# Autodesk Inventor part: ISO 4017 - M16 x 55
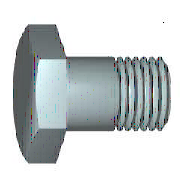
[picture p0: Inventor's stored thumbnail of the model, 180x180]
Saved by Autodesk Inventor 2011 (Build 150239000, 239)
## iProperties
Created: 2009-02
Part Number: ISO 4017 - M16 x 55
Material: Stainless Steel, 440C
Description: Hexagon head screws
Document SubType Name: Modeling
Standard: ISO 4017
Designer: V.de Jong
Standard Revision: Third edition 1999-08-15
Standards Organization: ISO
Language: en-US
Size Designation: M16 x 55
Categories: <MemberInstance><Categories><Category DisplayName="Fasteners" InternalName="e4da775c-781d-43d5-af7c-5136215cf5a6" Mnemonic="FSTN"><Category DisplayName="Bolts"
Density: 7.75 g/cm^3
IsCustomPart: 0
Author: V.de Jong
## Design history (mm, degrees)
body "Solid1"
workplane "Work Plane1"
revolve "Body" stored, may be unused: angle "d12" = 90 deg
sketch "Sketch2"
  geometry: L1 (0, 13.856)-(12, 6.928); L2 (12, 6.928)-(12, -6.928); L3 (12, -6.928)-(0, -13.856); L4 (0, -13.856)-(-12, -6.928); L5 (-12, -6.928)-(-12, 6.928); L6 (-12, 6.928)-(0, 13.856); 2 further points
  constraints: 12 end point, 1 coincident, 1 vertical, 11 other
  dimensions: "d11" = 24 distance between parallel lines of L5 L2 (= SW)
extrude "Head" join sketch "Sketch2" distance "d3" = 9.2 (= KOH - SD); taper "d4" = 0 deg
revolve "Chamfer1" stored, may be unused: angle "d21" = 90 deg
feature "Thread" dims "d15" = 49 (= GEL), "d16" = 0
chamfer "Chamfer2" distance "d6" = 1.2269 (= -0.5 x SPD + 0.5 x GD); stored, may be unused: second distance "d7" = 1.227 (computed from GUL), angle "d55" = 45 deg
sketch "Sketch1"
  geometry: L1 (0, 11.245)-(0, 8); L2 (6, 8)-(55, 8); L3 (55, 8)-(55, 0); L4 (55, 0)-(-0.8, 0); L5 (-11.96, 0)-(66.16, 0) reference; L6 (-0.8, 0)-(-0.8, 11.245); L7 (-0.8, 11.245)-(0, 11.245); L8 (6, 8)-(4.773, 8); L9 (4.773, 8)-(0, 8); L10 (0, -2.249)-(0, 13.494) reference
  constraints: 16 end point, 2 collinear, 2 perpendicular, 1 parallel
  dimensions: "d0" = 55 distance between parallel lines of L3 L1 (= NLG); "d1" = 49 distance from line of L2.start L3 (= GEL); "d2" = 16 diameter of L2 L4 (= GD); "d9" = 0.8001 distance between parallel lines of L6 L1 (computed from SD); "d10" = 22.49 diameter of L7 L4 (= SD2); "d13" = 1.227 distance of L2.start L8.end (computed from GAL); "d14" = 16 diameter of L9 L4 (= BDM)
sketch "Sketch4"
  geometry: L1 (-10, 12)-(-10, 13.856); L2 (-10, 13.856)-(-8.928, 13.856); L3 (-8.928, 13.856)-(-10, 12); L4 (-11.84, 0)-(1.04, 0) reference; L5 (-0.8, 13.856)-(-10, 13.856) reference; L6 (-10, 6.928)-(-10, 13.856) reference
  constraints: 6 end point, 2 collinear, 1 perpendicular, 1 vertical
  dimensions: "d5" = 30 deg angle of L3 L1 (= ANG1); "d19" = 24 diameter of L1.start L4 (= SW0)
other parameters: "NLG" = 55 [user parameter; used in 1 equation term], "GD" = 16 (= NND) [user parameter; used in 2 equation terms], "BDM" = 16 (= NND) [user parameter; used in 1 equation term], "KOH" = 10 [user parameter; used in 1 equation term], "GEL" = 49 [user parameter; used in 2 equation terms], "SW" = 24 [user parameter; used in 2 equation terms], "SW0" = 24 (= SW) [user parameter; used in 1 equation term], "SPD" = 13.5462 (= NND - 1.2269 x PTC) [user parameter; used in 1 equation term], "SD2" = 22.49 [user parameter; used in 2 equation terms], "SD" = 0.8 [user parameter; used in 2 equation terms], "ANG1" = 30 deg [user parameter; used in 1 equation term], "GAL" = 1.2269 (= 0.61345 x PTC) [user parameter; used in 1 equation term], "GUL" = 1.2269 (= 0.61345 x PTC) [user parameter; used in 1 equation term], "d8" = 0, "RR" = 0.6 [user parameter], "d57" = 0, "d58" = 0, "TPU" = 5 (computed from PTC) [user parameter], "GD1" = 13.5462 (= THREADDIA - 1.2269 x PTC) [user parameter], "THREADDIA" = 16 [user parameter; used in 1 equation term], "SDH" = 22.49 (= SD2) [user parameter], "SDHG" = 6 [user parameter], "TOA" = 30 deg [user parameter], "PTC" = 2 [user parameter; used in 5 equation terms], "NND" = 16 [user parameter; used in 3 equation terms], "E0" = 27.72 [user parameter]
